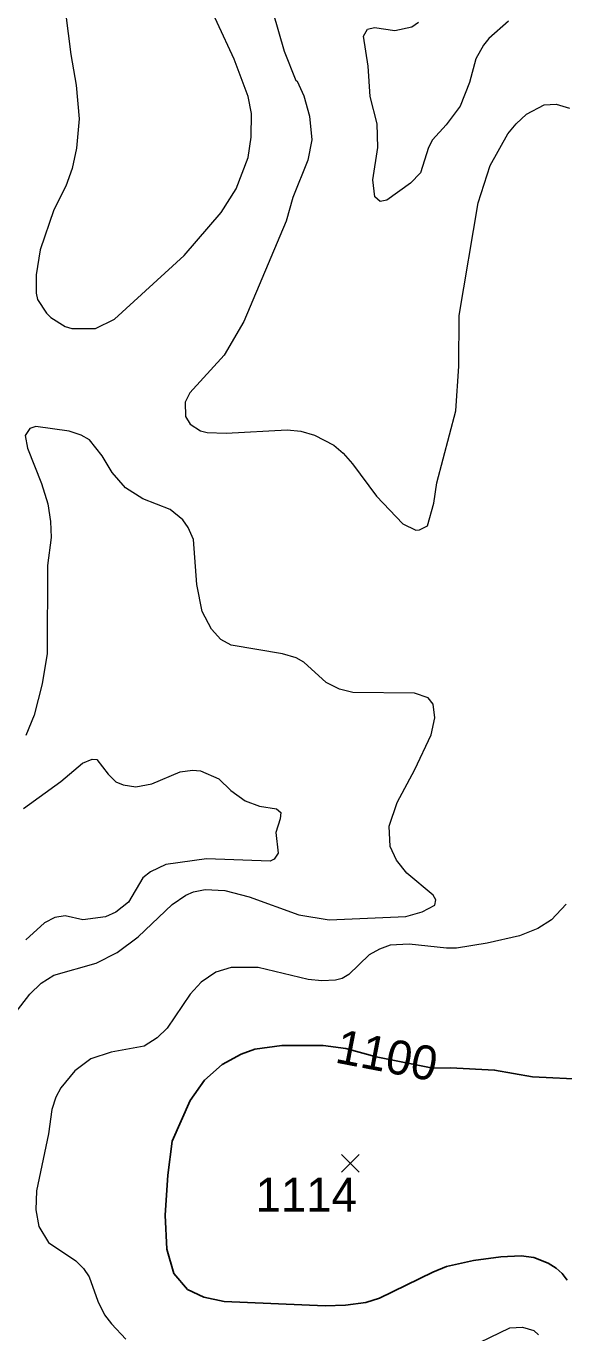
# Model space of a CAD drawing. Extents: x 265 to 291.4, y 7731.5 to 7759.6.
# Drawn here: x 278.902 to 280.165, y 7743.215 to 7746.284 of the extents above; entities that cross this region are included whole.
import ezdxf
from ezdxf.enums import TextEntityAlignment as Align

# ---------------------------------------------------------------- set-up
doc = ezdxf.new("R2010")
doc.units = 0
doc.header["$LTSCALE"] = 0.032
for name, color, linetype, lineweight in [('1', 7, 'Continuous', 25), ('2', 7, 'Continuous', 13), ('21', 7, 'Continuous', 25), ('61', 7, 'Continuous', 13)]:
    doc.layers.add(name, color=color, linetype=linetype, lineweight=lineweight)

msp = doc.modelspace()

# ---------------------------------------------------------------- linework, layer by layer
at = {"layer": '1'}
msp.add_lwpolyline([(280.1721, 7743.3387), (280.161, 7743.3546), (280.1467, 7743.3673), (280.1276, 7743.3785), (280.0942, 7743.392), (280.064, 7743.396), (280.0163, 7743.3936), (279.9526, 7743.3848), (279.889, 7743.3705), (279.8572, 7743.3578), (279.7315, 7743.2965), (279.6997, 7743.2862), (279.6519, 7743.2798), (279.6042, 7743.2782), (279.3671, 7743.2886), (279.3194, 7743.2989), (279.2812, 7743.3172), (279.2486, 7743.3546), (279.2327, 7743.4119), (279.2287, 7743.4915), (279.2351, 7743.5853), (279.2446, 7743.6649), (279.2868, 7743.7603), (279.321, 7743.8081), (279.3624, 7743.8454), (279.4069, 7743.8693), (279.4387, 7743.8812), (279.5024, 7743.89), (279.5994, 7743.89), (279.6527, 7743.8828), (279.7241, 7743.8629), (279.8569, 7743.8363), (279.8981, 7743.8376), (280.0019, 7743.8319), (280.091, 7743.816), (280.2183, 7743.8096)], dxfattribs=at)
at = {"layer": '2'}
for points in [[(278.9948, 7746.3154), (279.0068, 7746.2168), (279.0195, 7746.1452), (279.0267, 7746.0656), (279.0203, 7745.9972), (279.01, 7745.9495), (278.9956, 7745.9081), (278.967, 7745.8525), (278.9352, 7745.7586), (278.9256, 7745.6997), (278.9256, 7745.6568), (278.9288, 7745.6416), (278.9495, 7745.6098), (278.9598, 7745.5995), (278.9933, 7745.578), (279.0092, 7745.5732), (279.0649, 7745.5732), (279.1094, 7745.5955), (279.2733, 7745.7451), (279.36, 7745.8461), (279.395, 7745.9018), (279.4236, 7745.975), (279.43, 7746.0227), (279.4308, 7746.0784), (279.4236, 7746.1181), (279.3902, 7746.2057), (279.3107, 7746.3791)], [(279.4809, 7746.317), (279.5079, 7746.2247), (279.535, 7746.1563), (279.5382, 7746.1547), (279.5541, 7746.1197), (279.5676, 7746.072), (279.5732, 7746.0163), (279.5636, 7745.9686), (279.5286, 7745.8811), (279.5127, 7745.8254), (279.4133, 7745.5899), (279.3671, 7745.5112), (279.286, 7745.4221), (279.2757, 7745.4006), (279.2765, 7745.3672), (279.2868, 7745.3489), (279.3115, 7745.333), (279.3274, 7745.329), (279.3719, 7745.3274), (279.5151, 7745.3354), (279.5469, 7745.3322), (279.5787, 7745.3234), (279.6241, 7745.2996), (279.6464, 7745.2805), (279.6686, 7745.2558), (279.7243, 7745.1795), (279.7864, 7745.115), (279.8174, 7745.0999), (279.8253, 7745.1007), (279.8444, 7745.1103), (279.8595, 7745.1636), (279.8667, 7745.2113), (279.9112, 7745.3799), (279.9176, 7745.4849), (279.9184, 7745.6043), (279.9637, 7745.8684), (279.9916, 7745.9567), (280.033, 7746.0306), (280.0528, 7746.0545), (280.0767, 7746.0768), (280.1181, 7746.099), (280.1467, 7746.1006), (280.1777, 7746.0911)], [(280.0345, 7746.2955), (279.9884, 7746.2542), (279.9757, 7746.2391), (279.9582, 7746.2072), (279.9431, 7746.1516), (279.9208, 7746.0959), (279.8882, 7746.0521), (279.8564, 7746.0163), (279.8468, 7745.9988), (279.8277, 7745.9392), (279.8047, 7745.9145), (279.749, 7745.8747), (279.7331, 7745.8715), (279.7211, 7745.8827), (279.7163, 7745.9225), (279.7275, 7745.9988), (279.7259, 7746.0545), (279.71, 7746.1181), (279.7052, 7746.1897), (279.6941, 7746.2597), (279.7036, 7746.2764), (279.7203, 7746.2804), (279.7681, 7746.2732), (279.8078, 7746.282), (279.823, 7746.2931)], [(278.8548, 7743.9385), (278.9105, 7744.0101), (278.9376, 7744.0364), (278.967, 7744.0547), (279.0665, 7744.0833), (279.1158, 7744.1079), (279.1651, 7744.1453), (279.2446, 7744.2209), (279.2773, 7744.2432), (279.2948, 7744.2503), (279.3226, 7744.2559), (279.3687, 7744.2535), (279.426, 7744.2392), (279.5422, 7744.197), (279.6137, 7744.1851), (279.7935, 7744.1931), (279.8317, 7744.2034), (279.8619, 7744.2193), (279.8643, 7744.2321), (279.8579, 7744.2432), (279.7959, 7744.2949), (279.772, 7744.3251), (279.7569, 7744.3569), (279.7545, 7744.4047), (279.7728, 7744.4604), (279.815, 7744.5383), (279.8532, 7744.6195), (279.8619, 7744.6592), (279.8579, 7744.6911), (279.846, 7744.7062), (279.8142, 7744.7173), (279.6694, 7744.7189), (279.6376, 7744.7268), (279.6066, 7744.7419), (279.5541, 7744.7897), (279.5358, 7744.8), (279.504, 7744.8096), (279.3831, 7744.8302), (279.3592, 7744.843), (279.3369, 7744.8676), (279.3154, 7744.909), (279.3027, 7744.9727), (279.2947, 7745.0777), (279.2828, 7745.1063), (279.2701, 7745.1246), (279.2399, 7745.1484), (279.1762, 7745.1739), (279.1357, 7745.1994), (279.1038, 7745.2352), (279.0808, 7745.2749), (279.0505, 7745.3123), (279.0314, 7745.3234), (279.0028, 7745.3322), (278.9248, 7745.3433), (278.9105, 7745.3386), (278.8994, 7745.3219), (278.905, 7745.2924), (278.9384, 7745.2097), (278.9527, 7745.162), (278.959, 7745.1206), (278.9606, 7745.0824), (278.9519, 7745.0172), (278.9511, 7744.8104), (278.94, 7744.7388), (278.9209, 7744.6656), (278.901, 7744.6179)], [(278.8962, 7744.446), (278.9837, 7744.5097), (279.0346, 7744.5526), (279.0569, 7744.5622), (279.068, 7744.5614), (279.0943, 7744.5272), (279.1126, 7744.5089), (279.1301, 7744.5017), (279.1595, 7744.497), (279.1969, 7744.5041), (279.2637, 7744.5327), (279.2924, 7744.5367), (279.3115, 7744.5351), (279.3544, 7744.516), (279.383, 7744.489), (279.4165, 7744.4643), (279.4499, 7744.4516), (279.4896, 7744.4452), (279.5, 7744.4373), (279.4984, 7744.4222), (279.488, 7744.3904), (279.4936, 7744.3418), (279.4841, 7744.3275), (279.4753, 7744.3227), (279.3258, 7744.3283), (279.2303, 7744.3148), (279.1937, 7744.2973), (279.1762, 7744.2838), (279.142, 7744.2265), (279.1126, 7744.2026), (279.0887, 7744.1923), (279.0354, 7744.1851), (278.9933, 7744.1946), (278.9694, 7744.1907), (278.9455, 7744.1779), (278.901, 7744.1382)], [(280.1698, 7744.2217), (280.1356, 7744.1851), (280.1038, 7744.1644), (280.0608, 7744.1477), (279.9844, 7744.1302), (279.9128, 7744.1183), (279.889, 7744.1183), (279.8015, 7744.1278), (279.7569, 7744.1254), (279.7315, 7744.1159), (279.7076, 7744.1024), (279.6599, 7744.0562), (279.644, 7744.0475), (279.6281, 7744.0435), (279.5962, 7744.0419), (279.5644, 7744.0451), (279.4467, 7744.0729), (279.3831, 7744.0729), (279.3472, 7744.0618), (279.3131, 7744.0387), (279.2872, 7744.0106), (279.2335, 7743.9306), (279.2096, 7743.9075), (279.1794, 7743.8884), (279.1015, 7743.8741), (279.0537, 7743.8582), (279.0163, 7743.8303), (278.9837, 7743.7906), (278.9718, 7743.7683), (278.9622, 7743.7397), (278.9543, 7743.6824), (278.9264, 7743.5487), (278.9248, 7743.5042), (278.932, 7743.4644), (278.9543, 7743.427), (279.0187, 7743.3841), (279.037, 7743.3658), (279.0497, 7743.3467), (279.0704, 7743.2894), (279.0863, 7743.2576), (279.1022, 7743.2361), (279.1364, 7743.2003)], [(279.9208, 7743.1701), (280.0377, 7743.2265), (280.0672, 7743.2281), (280.0942, 7743.2202), (280.1053, 7743.2106)]]:
    msp.add_lwpolyline(points, dxfattribs=at)
at = {"layer": '21'}
for p, q in [((279.6426, 7743.6338), (279.6838, 7743.5926)), ((279.6838, 7743.6338), (279.6426, 7743.5926))]:
    msp.add_line(p, q, dxfattribs=at)

# ---------------------------------------------------------------- texts
at = {"layer": '61'}
msp.add_text('1100', height=0.08, rotation=349.094, dxfattribs=at).set_placement((279.7416, 7743.8278), align=Align.CENTER)
msp.add_text('1114', height=0.08, dxfattribs=at).set_placement((279.5596, 7743.4995), align=Align.CENTER)

doc.saveas('drawing.dxf')
